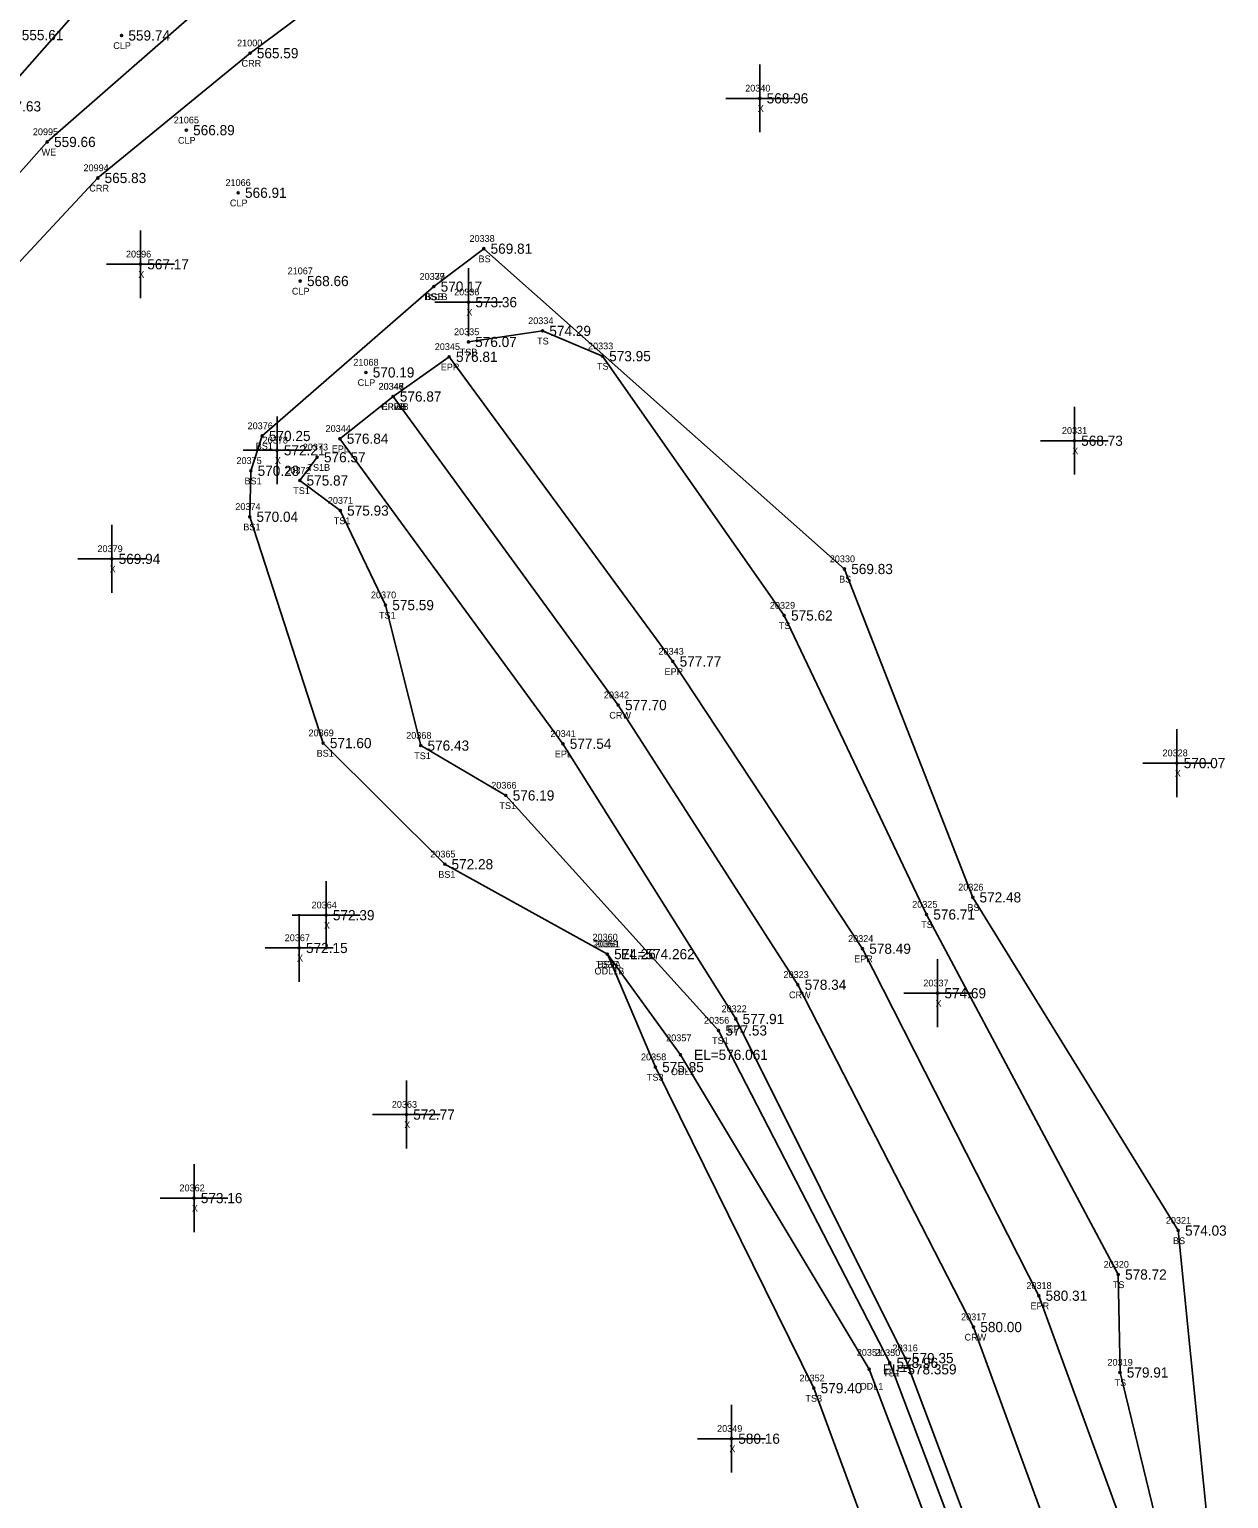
# Model space of a CAD drawing. Extents: x 1695443 to 1696344, y 1087542 to 1090645.
# Drawn here: x 1695877.6 to 1696054.4, y 1088830.4 to 1089047 of the extents above; entities that cross this region are included whole.
import ezdxf

# ---------------------------------------------------------------- set-up
doc = ezdxf.new("R2010")
doc.units = 0
for name, color, linetype in [('RD_DTM_BkLn1', 7, 'Continuous'), ('RD_DTM_BkLn2', 7, 'Continuous'), ('RD_DTM_BkLn_txCode', 7, 'Continuous'), ('RD_EX_H2O', 7, 'Continuous'), ('RD_EX_H2O_txCode', 7, 'Continuous'), ('RD_EX_Misc', 7, 'Continuous'), ('RD_EX_Misc_txCode', 7, 'Continuous'), ('RD_EX_Road', 7, 'Continuous'), ('RD_EX_Road_txCode', 7, 'Continuous'), ('RD_EX_TX_H2O_ELEV', 7, 'Continuous'), ('RD_EX_TX_Misc_ELEV', 7, 'Continuous'), ('RD_EX_TX_Road_ELEV', 7, 'Continuous'), ('RD_HC_Survey_ELEV', 7, 'Continuous'), ('RD_HC_Survey_txCode', 7, 'Continuous'), ('RD_SMD_Locator', 7, 'Continuous')]:
    doc.layers.add(name, color=color, linetype=linetype)

msp = doc.modelspace()

# ---------------------------------------------------------------- linework, layer by layer
at = {"layer": 'RD_DTM_BkLn1'}
for points in [[(1695519.05, 1088717.19), (1695621.07, 1088784.34), (1695706.03, 1088842.06), (1695754.64, 1088904.72), (1695822.43, 1088986.95), (1695872.19, 1089035.65), (1695897.24, 1089064.09), (1695953.83, 1089097.9), (1696039.66, 1089119.12), (1696131.31, 1089103.56), (1696189.39, 1089073.13), (1696217.04, 1089023.97), (1696212.37, 1088964.66)], [(1695869.23, 1087563.38), (1695882.71, 1087666.87), (1695895.39, 1087768.85), (1695908.05, 1087871.3), (1695919.71, 1087974.19), (1695925.35, 1088026.13), (1695931.27, 1088077.73), (1695937.88, 1088128.75), (1695945.4, 1088182.97), (1695952.48, 1088232.38), (1695961.74, 1088286.36), (1695971.36, 1088336.92), (1695982.91, 1088390.82), (1696009.16, 1088497.22), (1696035.45, 1088601.7), (1696045.5, 1088655.66), (1696049.03, 1088705.78), (1696045.47, 1088756.42), (1696033.82, 1088809.1), (1696016.78, 1088855.71), (1695990.89, 1088906.17), (1695964.41, 1088947.39), (1695931.21, 1088992.88)]]:
    msp.add_lwpolyline(points, dxfattribs=at)
at = {"layer": 'RD_DTM_BkLn2'}
for points in [[(1695957.06, 1088113.83), (1695958.4, 1088124.86), (1695969.72, 1088175.5), (1695984.45, 1088233.12), (1695986.34, 1088280.33), (1695995.02, 1088332.7), (1696009.2, 1088386.54), (1696038.3, 1088489.24), (1696061.78, 1088594.39), (1696062.98, 1088655.37), (1696069.05, 1088704.28), (1696065.26, 1088759.68), (1696052.53, 1088814.08), (1696046.96, 1088869.93), (1696016.66, 1088919.05), (1695997.75, 1088967.45), (1695944.59, 1089014.67), (1695937.23, 1089009.08)], [(1695962.8, 1088910.68), (1695938.83, 1088923.93), (1695920.9, 1088941.79), (1695910.08, 1088975.15), (1695910.25, 1088981.93), (1695911.91, 1088987.06), (1695937.23, 1089009.08)], [(1696049.23, 1088599.85), (1696058.32, 1088654.25), (1696063.16, 1088705.06), (1696059.06, 1088758.94), (1696047.37, 1088812.02), (1696038.37, 1088849.01), (1696038.12, 1088863.45), (1696009.85, 1088916.52), (1695988.88, 1088960.6), (1695962.07, 1088998.83), (1695953.25, 1089002.55), (1695942.32, 1089000.92)], [(1695916.78, 1088084), (1695925.73, 1088132.37), (1695932.55, 1088186.85), (1695940.12, 1088233.39), (1695949.48, 1088288.14), (1695959.7, 1088339.01), (1695971.73, 1088394.21), (1695997.36, 1088500.21), (1696023.08, 1088603.25), (1696032.92, 1088656.94), (1696036.1, 1088705.18), (1696032.76, 1088754.54), (1696021.34, 1088805.78), (1696004.42, 1088850.43), (1695979.2, 1088899.43), (1695947.85, 1088934.07), (1695935.29, 1088941.42), (1695930.1, 1088962.13), (1695923.44, 1088976.06), (1695917.46, 1088980.5), (1695920.03, 1088983.92)], [(1695811.33, 1088056.44), (1695848.8, 1088075.62), (1695896.28, 1088098.14), (1695916.78, 1088084), (1695919.84, 1088133.52), (1695923.64, 1088187.73), (1695930.8, 1088232.96), (1695939.58, 1088289.44), (1695949.3, 1088339.9), (1695960.86, 1088397.31), (1695988.69, 1088500.86), (1696013.19, 1088605.35), (1696020.87, 1088659.75), (1696023.4, 1088706.14), (1696018.3, 1088755.38), (1696009.58, 1088802.31), (1695993.24, 1088846.7), (1695969.88, 1088894.03), (1695962.8, 1088910.68)]]:
    msp.add_lwpolyline(points, dxfattribs=at)
at = {"layer": 'RD_EX_H2O'}
for points in [[(1695518.5, 1088708.22), (1695626.45, 1088775.86), (1695695.79, 1088824.57), (1695753.51, 1088889.68), (1695821.81, 1088964.67), (1695880.24, 1089030.4), (1695903.5, 1089050.75), (1695958.92, 1089087.13), (1696042.79, 1089112.69), (1696142.64, 1089092.08), (1696193.08, 1089060.79), (1696207.36, 1089030.79), (1696205.38, 1088967.18), (1696218.5, 1088901.4)], [(1695520.92, 1088704.05), (1695627.53, 1088770.84), (1695697.51, 1088817.15), (1695757.08, 1088884.85), (1695828.4, 1088961.5), (1695887.69, 1089025.09), (1695910.13, 1089043.49), (1695963.83, 1089083.42), (1696041.69, 1089105.91), (1696137.07, 1089082.48), (1696174.24, 1089034.61), (1696185.76, 1089011.54), (1696200.45, 1088973.14), (1696214.06, 1088899.28)], [(1695916.78, 1088084), (1695923.72, 1088132.78), (1695929.91, 1088186.51), (1695936.75, 1088234.45), (1695946.8, 1088289.18), (1695957.47, 1088339.74), (1695969.14, 1088394.61), (1695994.85, 1088500.6), (1696021.07, 1088603.21), (1696031.1, 1088657.25), (1696033.92, 1088705.19), (1696029.81, 1088754.45), (1696018.23, 1088805.15), (1696001.4, 1088849.48), (1695973.58, 1088895.84), (1695962.8, 1088910.68)]]:
    msp.add_lwpolyline(points, dxfattribs=at)
at = {"layer": 'RD_EX_Misc'}
for p, q in [((1695985.28, 1089031.83), (1695985.28, 1089041.83)), ((1695980.28, 1089036.83), (1695990.28, 1089036.83)), ((1695893.98, 1089007.37), (1695893.98, 1089017.37)), ((1695888.98, 1089012.37), (1695898.98, 1089012.37)), ((1695942.35, 1089001.78), (1695942.35, 1089011.78)), ((1695937.35, 1089006.78), (1695947.35, 1089006.78)), ((1696031.65, 1088981.36), (1696031.65, 1088991.36)), ((1695914.11, 1088979.95), (1695914.11, 1088989.95)), ((1695909.11, 1088984.95), (1695919.11, 1088984.95)), ((1696026.65, 1088986.36), (1696036.65, 1088986.36)), ((1695889.76, 1088963.94), (1695889.76, 1088973.94)), ((1695884.76, 1088968.94), (1695894.76, 1088968.94)), ((1696046.76, 1088933.84), (1696046.76, 1088943.84)), ((1696041.76, 1088938.84), (1696051.76, 1088938.84)), ((1695921.34, 1088911.42), (1695921.34, 1088921.42)), ((1695916.34, 1088916.42), (1695926.34, 1088916.42)), ((1695917.38, 1088906.59), (1695917.38, 1088916.59)), ((1695912.38, 1088911.59), (1695922.38, 1088911.59)), ((1696011.49, 1088899.92), (1696011.49, 1088909.92)), ((1696006.49, 1088904.92), (1696016.49, 1088904.92)), ((1695933.18, 1088882.03), (1695933.18, 1088892.03)), ((1695928.18, 1088887.03), (1695938.18, 1088887.03)), ((1695901.87, 1088869.72), (1695901.87, 1088879.72)), ((1695896.87, 1088874.72), (1695906.87, 1088874.72)), ((1695981.1, 1088834.25), (1695981.1, 1088844.25)), ((1695976.1, 1088839.25), (1695986.1, 1088839.25))]:
    msp.add_line(p, q, dxfattribs=at)
at = {"layer": 'RD_EX_Road'}
for points in [[(1695879.87, 1087561.29), (1695893.33, 1087665.71), (1695905.96, 1087767.16), (1695918.66, 1087869.54), (1695930.87, 1087972.82), (1695936.26, 1088023.68), (1695942.14, 1088076.32), (1695948.07, 1088128.17), (1695955.04, 1088181.4), (1695962.88, 1088230.72), (1695971.68, 1088284.64), (1695982.02, 1088336.12), (1695993.28, 1088388.48), (1696018.75, 1088494.48), (1696045.23, 1088599.95), (1696055.72, 1088654.41), (1696060.15, 1088705.35), (1696055.83, 1088758.02), (1696044.01, 1088812.16), (1696026.4, 1088860.33), (1696000.41, 1088911.48), (1695972.46, 1088953.82), (1695939.48, 1088998.73), (1695931.21, 1088992.88)], [(1696024.81, 1088603.86), (1696034.83, 1088656.78), (1696038.52, 1088705.77), (1696034.91, 1088754.94), (1696023.53, 1088806.4), (1696006.7, 1088851.13), (1695981.74, 1088901.12), (1695956.26, 1088941.69), (1695923.39, 1088986.66), (1695931.21, 1088992.88)]]:
    msp.add_lwpolyline(points, dxfattribs=at)
at = {"layer": 'RD_SMD_Locator'}
for centre in [(1695891.2, 1089046.1), (1695910.13, 1089043.49), (1695985.28, 1089036.83), (1695900.74, 1089032.14), (1695880.24, 1089030.4), (1695887.69, 1089025.09), (1695908.39, 1089022.91), (1695944.59, 1089014.67), (1695893.98, 1089012.37), (1695917.53, 1089009.9), (1695937.23, 1089009.08), (1695937.23, 1089009.08), (1695942.35, 1089006.78), (1695953.25, 1089002.55), (1695942.32, 1089000.92), (1695939.48, 1088998.73), (1695962.07, 1088998.83), (1695927.22, 1088996.43), (1695931.21, 1088992.88), (1695931.21, 1088992.88), (1695931.21, 1088992.88), (1695911.91, 1088987.06), (1695923.39, 1088986.66), (1695914.11, 1088984.95), (1696031.65, 1088986.36), (1695920.03, 1088983.92), (1695910.25, 1088981.93), (1695917.46, 1088980.5), (1695923.44, 1088976.06), (1695910.08, 1088975.15), (1695889.76, 1088968.94), (1695997.75, 1088967.45), (1695930.1, 1088962.13), (1695988.88, 1088960.6), (1695972.46, 1088953.82), (1695964.41, 1088947.39), (1695920.9, 1088941.79), (1695935.29, 1088941.42), (1695956.26, 1088941.69), (1696046.76, 1088938.84), (1695947.85, 1088934.07), (1695938.83, 1088923.93), (1696016.66, 1088919.05), (1695921.34, 1088916.42), (1696009.85, 1088916.52), (1695917.38, 1088911.59), (1696000.41, 1088911.48), (1695962.8, 1088910.68), (1695962.8, 1088910.68), (1695962.8, 1088910.68), (1695990.89, 1088906.17), (1696011.49, 1088904.92), (1695981.74, 1088901.12), (1695979.2, 1088899.43), (1695973.58, 1088895.84), (1695969.88, 1088894.03), (1695933.18, 1088887.03), (1695901.87, 1088874.72), (1696046.96, 1088869.93), (1696038.12, 1088863.45), (1696026.4, 1088860.33), (1696016.78, 1088855.71), (1696004.42, 1088850.43), (1696006.7, 1088851.13), (1696001.4, 1088849.48), (1696038.37, 1088849.01), (1695993.24, 1088846.7), (1695981.1, 1088839.25)]:
    msp.add_circle(centre, 0.15, dxfattribs=at)

# ---------------------------------------------------------------- texts
at = {"layer": 'RD_DTM_BkLn_txCode'}
for s, p in [('20338', (1695942.48, 1089015.67)), ('BS', (1695943.81, 1089012.67)), ('20339', (1695935.12, 1089010.08)), ('20377', (1695935.12, 1089010.08)), ('BS1B', (1695935.82, 1089007.08)), ('BSB', (1695935.98, 1089007.08)), ('20334', (1695951.13, 1089003.55)), ('20335', (1695940.2, 1089001.92)), ('TSB', (1695941.05, 1088998.92)), ('TS', (1695952.45, 1089000.55)), ('20333', (1695959.95, 1088999.83)), ('TS', (1695961.27, 1088996.83)), ('20376', (1695909.77, 1088988.06)), ('BS1', (1695910.97, 1088985.06)), ('20373', (1695917.91, 1088984.92)), ('20375', (1695908.13, 1088982.93)), ('20372', (1695915.34, 1088981.5)), ('TS1B', (1695918.59, 1088981.92)), ('BS1', (1695909.31, 1088979.93)), ('TS1', (1695916.5, 1088978.5)), ('20374', (1695907.96, 1088976.15)), ('20371', (1695921.6, 1088977.06)), ('BS1', (1695909.14, 1088973.15)), ('TS1', (1695922.48, 1088974.06)), ('20330', (1695995.59, 1088968.45)), ('BS', (1695996.97, 1088965.45)), ('20370', (1695927.95, 1088963.13)), ('TS1', (1695929.14, 1088960.13)), ('20329', (1695986.76, 1088961.6)), ('TS', (1695988.09, 1088958.6)), ('20369', (1695918.75, 1088942.79)), ('20368', (1695933.15, 1088942.42)), ('BS1', (1695919.95, 1088939.79)), ('TS1', (1695934.33, 1088939.42)), ('20366', (1695945.69, 1088935.07)), ('TS1', (1695946.89, 1088932.07)), ('20365', (1695936.69, 1088924.93)), ('BS1', (1695937.88, 1088921.93)), ('20326', (1696014.52, 1088920.05)), ('20325', (1696007.74, 1088917.52)), ('BS', (1696015.88, 1088917.05)), ('TS', (1696009.06, 1088914.52)), ('20359', (1695960.68, 1088911.68)), ('20361', (1695960.94, 1088911.68)), ('TS3B', (1695961.08, 1088908.68)), ('BS1A', (1695961.36, 1088908.68)), ('20356', (1695977.05, 1088900.43)), ('TS1', (1695978.24, 1088897.43)), ('20358', (1695967.76, 1088895.03)), ('TS3', (1695968.63, 1088892.03)), ('20321', (1696045.13, 1088870.93)), ('BS', (1696046.18, 1088867.93)), ('20320', (1696035.96, 1088864.45)), ('TS', (1696037.32, 1088861.45)), ('20350', (1696002.26, 1088851.43)), ('20319', (1696036.53, 1088850.01)), ('20352', (1695991.12, 1088847.7)), ('TS1', (1696003.45, 1088848.43)), ('TS', (1696037.57, 1088847.01)), ('TS3', (1695992, 1088844.7))]:
    msp.add_text(s, height=1, dxfattribs=at).set_placement(p)
at = {"layer": 'RD_EX_H2O_txCode'}
for s, p in [('21000', (1695908.22, 1089044.49)), ('CRR', (1695908.88, 1089041.49)), ('20995', (1695878.12, 1089031.4)), ('WE', (1695879.4, 1089028.4)), ('20994', (1695885.58, 1089026.09)), ('CRR', (1695886.44, 1089023.09)), ('20360', (1695960.61, 1088912.68)), ('ODL1B', (1695960.91, 1088907.68)), ('20357', (1695971.47, 1088897.84)), ('ODL1', (1695972.17, 1088892.84)), ('20351', (1695999.57, 1088851.48)), ('ODL1', (1695999.99, 1088846.48))]:
    msp.add_text(s, height=1, dxfattribs=at).set_placement(p)
at = {"layer": 'RD_EX_Misc_txCode'}
for s, p in [('20340', (1695983.12, 1089037.83)), ('X', (1695984.97, 1089034.83)), ('20996', (1695891.84, 1089013.37)), ('X', (1695893.66, 1089010.37)), ('20336', (1695940.21, 1089007.78)), ('X', (1695942.03, 1089004.78)), ('20378', (1695911.99, 1088985.95)), ('20331', (1696029.81, 1088987.36)), ('X', (1696031.33, 1088984.36)), ('X', (1695913.79, 1088982.95)), ('20379', (1695887.64, 1088969.94)), ('X', (1695889.44, 1088966.94)), ('20328', (1696044.64, 1088939.84)), ('X', (1696046.44, 1088936.84)), ('20364', (1695919.2, 1088917.42)), ('X', (1695921.02, 1088914.42)), ('20367', (1695915.24, 1088912.59)), ('X', (1695917.06, 1088909.59)), ('20337', (1696009.38, 1088905.92)), ('X', (1696011.18, 1088902.92)), ('20363', (1695931.03, 1088888.03)), ('X', (1695932.86, 1088885.03)), ('20362', (1695899.73, 1088875.72)), ('X', (1695901.56, 1088872.72)), ('20349', (1695978.98, 1088840.25)), ('X', (1695980.78, 1088837.25))]:
    msp.add_text(s, height=1, dxfattribs=at).set_placement(p)
at = {"layer": 'RD_EX_Road_txCode'}
for s, p in [('20345', (1695937.36, 1088999.73)), ('EPR', (1695938.25, 1088996.73)), ('20346', (1695929.06, 1088993.88)), ('20347', (1695929.09, 1088993.88)), ('EPRB', (1695929.5, 1088990.88)), ('EPLB', (1695929.53, 1088990.88)), ('20344', (1695921.27, 1088987.66)), ('EPL', (1695922.18, 1088984.66)), ('20343', (1695970.34, 1088954.82)), ('EPR', (1695971.23, 1088951.82)), ('20341', (1695954.43, 1088942.69)), ('EPL', (1695955.06, 1088939.69)), ('20324', (1695998.29, 1088912.48)), ('EPR', (1695999.18, 1088909.48)), ('20322', (1695979.63, 1088902.12)), ('EPL', (1695980.54, 1088899.12)), ('20318', (1696024.57, 1088861.33)), ('EPR', (1696025.18, 1088858.33)), ('20316', (1696004.84, 1088852.13)), ('EPL', (1696005.49, 1088849.13))]:
    msp.add_text(s, height=1, dxfattribs=at).set_placement(p)
at = {"layer": 'RD_EX_TX_H2O_ELEV'}
for s, p in [('565.59', (1695911.13, 1089042.74)), ('559.66', (1695881.24, 1089029.65)), ('565.83', (1695888.69, 1089024.34)), ('EL=574.262', (1695964.8, 1088909.93)), ('EL=576.061', (1695975.58, 1088895.09)), ('EL=578.359', (1696003.4, 1088848.73))]:
    msp.add_text(s, height=1.5, dxfattribs=at).set_placement(p)
at = {"layer": 'RD_EX_TX_Misc_ELEV'}
for s, p in [('568.96', (1695986.28, 1089036.08)), ('557.63', (1695873.19, 1089034.9)), ('569.81', (1695945.59, 1089013.92)), ('567.17', (1695894.98, 1089011.62)), ('570.17', (1695938.23, 1089008.33)), ('570.17', (1695938.23, 1089008.33)), ('573.36', (1695943.35, 1089006.03)), ('574.29', (1695954.25, 1089001.8)), ('576.07', (1695943.32, 1089000.17)), ('573.95', (1695963.07, 1088998.08)), ('570.25', (1695912.91, 1088986.31)), ('568.73', (1696032.65, 1088985.61)), ('572.21', (1695915.11, 1088984.2)), ('576.57', (1695921.03, 1088983.17)), ('570.28', (1695911.25, 1088981.18)), ('575.87', (1695918.46, 1088979.75)), ('575.93', (1695924.44, 1088975.31)), ('570.04', (1695911.08, 1088974.4)), ('569.94', (1695890.76, 1088968.19)), ('569.83', (1695998.75, 1088966.7)), ('575.59', (1695931.1, 1088961.38)), ('575.62', (1695989.88, 1088959.85)), ('571.60', (1695921.9, 1088941.04)), ('576.43', (1695936.29, 1088940.67)), ('570.07', (1696047.76, 1088938.09)), ('576.19', (1695948.85, 1088933.32)), ('572.28', (1695939.83, 1088923.18)), ('572.48', (1696017.66, 1088918.3)), ('572.39', (1695922.34, 1088915.67)), ('576.71', (1696010.85, 1088915.77)), ('572.15', (1695918.38, 1088910.84)), ('574.26', (1695963.8, 1088909.93)), ('574.26', (1695963.8, 1088909.93)), ('574.69', (1696012.49, 1088904.17)), ('577.53', (1695980.2, 1088898.68)), ('575.85', (1695970.88, 1088893.28)), ('572.77', (1695934.18, 1088886.28)), ('573.16', (1695902.87, 1088873.97)), ('574.03', (1696047.96, 1088869.18)), ('578.72', (1696039.12, 1088862.7)), ('578.96', (1696005.42, 1088849.68)), ('579.91', (1696039.37, 1088848.26)), ('579.40', (1695994.24, 1088845.95)), ('580.16', (1695982.1, 1088838.5))]:
    msp.add_text(s, height=1.5, dxfattribs=at).set_placement(p)
at = {"layer": 'RD_EX_TX_Road_ELEV'}
for s, p in [('576.81', (1695940.48, 1088997.98)), ('576.87', (1695932.21, 1088992.13)), ('576.87', (1695932.21, 1088992.13)), ('576.84', (1695924.39, 1088985.91)), ('577.77', (1695973.46, 1088953.07)), ('577.54', (1695957.26, 1088940.94)), ('578.49', (1696001.41, 1088910.73)), ('577.91', (1695982.74, 1088900.37)), ('580.31', (1696027.4, 1088859.58)), ('579.35', (1696007.7, 1088850.38))]:
    msp.add_text(s, height=1.5, dxfattribs=at).set_placement(p)
at = {"layer": 'RD_HC_Survey_ELEV'}
for s, p in [('555.61', (1695876.48, 1089045.4)), ('559.74', (1695892.2, 1089045.35)), ('566.89', (1695901.74, 1089031.39)), ('566.91', (1695909.39, 1089022.16)), ('568.66', (1695918.53, 1089009.15)), ('570.19', (1695928.22, 1088995.68)), ('576.87', (1695932.21, 1088992.13)), ('577.70', (1695965.41, 1088946.64)), ('578.34', (1695991.89, 1088905.42)), ('580.00', (1696017.78, 1088854.96))]:
    msp.add_text(s, height=1.5, dxfattribs=at).set_placement(p)
at = {"layer": 'RD_HC_Survey_txCode'}
for s, p in [('CLP', (1695889.97, 1089044.1)), ('21065', (1695898.88, 1089033.14)), ('CLP', (1695899.51, 1089030.14)), ('21066', (1695906.51, 1089023.91)), ('CLP', (1695907.16, 1089020.91)), ('21067', (1695915.67, 1089010.9)), ('CLP', (1695916.3, 1089007.9)), ('21068', (1695925.36, 1088997.43)), ('CLP', (1695925.99, 1088994.43)), ('20348', (1695929.09, 1088993.88)), ('CRWB', (1695929.42, 1088990.88)), ('20342', (1695962.29, 1088948.39)), ('CRW', (1695963.09, 1088945.39)), ('20323', (1695988.77, 1088907.17)), ('CRW', (1695989.58, 1088904.17)), ('20317', (1696014.94, 1088856.71)), ('CRW', (1696015.46, 1088853.71))]:
    msp.add_text(s, height=1, dxfattribs=at).set_placement(p)

doc.saveas('drawing.dxf')
